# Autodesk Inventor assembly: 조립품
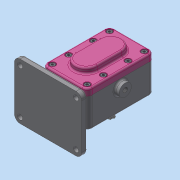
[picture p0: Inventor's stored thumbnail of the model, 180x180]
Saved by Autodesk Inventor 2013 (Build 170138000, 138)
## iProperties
Created: 2020-04
Part Number: 조립품
Document SubType Name: Assembly
Designer: dgall
Author: dgall
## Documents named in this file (10)
- C:\Users\dgall\Desktop\700407V1032\조립품.iam
- C:\Users\dgall\Desktop\700407V1032\본체.ipt
- C:\Users\dgall\Desktop\700407V1032\메인축.ipt
- C:\Users\dgall\Desktop\700407V1032\오일 실 16 28 7.ipt
- C:\Users\dgall\Desktop\700407V1032\베어링부시.ipt
- C:\Users\dgall\Desktop\700407V1032\스퍼기어.ipt
- C:\Users\dgall\Desktop\700407V1032\키 6 x 6 x 18.ipt
- C:\Users\dgall\Desktop\700407V1032\서브축.ipt
- C:\Users\dgall\Desktop\700407V1032\커버.ipt
- C:\Users\dgall\Desktop\700407V1032\볼트 M5.ipt
